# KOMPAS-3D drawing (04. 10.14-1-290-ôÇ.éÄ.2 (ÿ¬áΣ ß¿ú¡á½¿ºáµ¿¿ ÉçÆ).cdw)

Views: Вид спереди. Двери не показаны, Вид 2, Вид 3
Referenced files: ЗРУ 10кВ ПС527.cdw
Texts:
  Корюкин Александр Сергеевич
  Последний номер ВЭ
  Последний номер ВЭ в сечении
  Колонна
  Лестница
  Марш ЛМФ42.15.18-5 ГОСТ 9818-85
  Марш ЛМП57.11.18-5 ГОСТ 9818-85
  Марш ЛМФ42.14.18-5 ГОСТ 9818-85
  Марш ЛМП57.11.14-5 ГОСТ 9818-85
  Марш ЛМ30.12.15-4 ГОСТ 9818-85
  Марш ЛМ30.11.15-4 ГОСТ 9818-85
  Марш ЛМФ42.12.18-5 ГОСТ 9818-85
  Марш ЛМФ49.17.21-5 ГОСТ 9818-85
  Марш ЛМП57.11.15-5 ГОСТ 9818-85
  Марш ЛМ27.12.14-4Л ГОСТ 9818-85
  Марш ЛМФ49.14.21-5 ГОСТ 9818-85
  Марш ЛМФ49.15.21-5 ГОСТ 9818-85
  Марш ЛМП60.11.15-5 ГОСТ 9818-85
  Марш ЛМ27.11.14-4Л ГОСТ 9818-85
  Марш ЛМФ39.14.17-5 ГОСТ 9818-85
  Марш ЛМФ39.15.17-5 ГОСТ 9818-85
  Марш ЛМ27.12.14-4 ГОСТ 9818-85
  Марш ЛМ27.11.14-4 ГОСТ 9818-85
  Марш ЛМФ39.12.17-5 ГОСТ 9818-85
  Марш ЛМП57.11.17-5 ГОСТ 9818-85
  Марш ЛМП60.11.17-5 ГОСТ 9818-85
  Стена
  Блоки фундаментные 130
  Блоки фундаментные 400
  Блоки фундаментные 500
  Блоки фундаментные 600
  Текст на чертеже
  Размерные надписи
  Шероховатость
  Линия-выноска #1
  Линия-выноска #2
  Линия-выноска #3
  Отклонения формы и база
  Заголовок таблицы
  Ячейка таблицы
  Стрелка вида
  Обозначение изменения
  Фигурная скобка
  Номер узла
  Марка координационной оси
  VRCB
  Выносная надпись
  Обозначение узла
  Марка/позиционное обозначение с линией-выноской
  Марка/позиционное обозначение на линии
  Марка/позиционное обозначение без линии-выноски
  Лит-Масса-Масштаб
  Материал-Предприятие
  Normal
  Additional DXF text style 0
  Обычный
  Термин
  Список определений
  Адрес
  Цитаты
  Форматированный
  Courier New
  Z-конец формы
  Z-начало формы
  Подпись в квадратике
  цепи
  Title Specification
  Body Specification ( left align )
  Body Specificaton ( centered )
  Body Text
  ссылки
  табл
  Без имени
  Тексты. 3,2
  ЗОНА_привяз
  heading 1
  Знак Знак Знак Знак Знак Знак
  Verdana
  Body Text 3
  Title
  txt
  MS Sans Serif
  Simplex
  Txt
  ТекстШаг1
  Денис
  heading 8
  heading 3
  heading 6
  heading 7
  russ
  ООббыыччнныыйй
  ТТееррммиинн
  ССппииссоокк ооппррееддееллеенниийй
  ААддрреесс
  ЦЦииттааттыы
  ФФооррммааттиирроовваанннныыйй
  Z-ккооннеецц ффооррммыы
  Z-ннааччааллоо ффооррммыы
  Абзац Знак
  heading 2
  heading 4
  heading 5
  heading 9
  Клеммник текст
  текст переноса
  Маркировка
  клеммы, контакты
  тексты табл
  AGOpus
  footer
  Definition Term
  Definition List
  Address
  Blockquote
  Preformatted
  z-Bottom of Form
  z-Top of Form
  Состав чартежа
  ячейка табл.
  маркировка
  Аппараты
  rustxt
  Table Contents
  Table Heading
  Tahoma
  подписи
  Ссылки
  Пояснения
  Монтаж.ед.
  ахтунг!!
  полезная площадь
  лампочки
  Фасад шкафа
  Перечень надписей
  Монтажная
  единица
  KH1
  Позиционное
  обозначение
  по схеме
  КН2
  SG1
  В рамке под
  аппаратом
  Место
  надписи
  KH1. Отключение В-110 1Т от РЗТ (ЭМО1)
  Текст надписи
  KH2. Отключение В-110 1Т от РЗТ (ЭМО2)
  SG1. Токовые цепи РЗТ 1Т
  KH1. Отключение В-110 2Т от РЗТ (ЭМО1)
  KH2. Отключение В-110 2Т от РЗТ (ЭМО2)
  SG1. Токовые цепи РЗТ 2Т
  Наименование монтажной единицы
  Номер монтажной единицы
  Номер схемы электрической
  принципиальной
  Номер чертежа клеммного ряда
  Перечень монтажных единиц и чертежей
  Сигнализация РЗТ
  Примечания:
  шкафа - серый;
  изолированным проводом сечением не менее 1,5 мм 2 , токовые цепи - сечением 4 мм 2 ;
  основной конструкции на болты. Медная полоса должна обеспечивать возможность присоединения
  кабелей с целью концевой разделки и заземления экранов с помощью металлических зажимов.
  CONTINUOUS0
  GOST2.303 6_RGB_0_0_0_SC_0.1_THICK_0.13
  POLYLINE_STYLE_0.18_RGB_0_0_0
  K5LT_BASIC_RGB_0_0_255_THICK_0.6
  Стили документа
  Общеподстанционный пункт
  управления тип III из
  унифицированных конструкций
  Общий вид щита  управления
  с мнемонической схемой
  Чертеж общего вида
  Шкаф сигнализации РЗТ.
  Чертёж общего вида.
  Н.контр
  Борисов
  Разраб.
  Реконструкция ПС 110 кВ Опорная
  (замена трансформаторов 16МВА на 40МВА)
Dimensions and other numbers on the sheet: 10/14-1-290-УА.ВО.2; 5; 0; 7; 3,2_зона не привяз; 3,2 (надписи); 2.5; 3,2_; 2,5_3; 2,5 (контакты, клеммы); 2,5_01; 3,5_01; 2,3_; 5_заголовок; 3,5_tabl; 3.5; 2,5; 1,8; 3,2; 2.5 курсив; 2,5 грязносинь; 3,5; 3,2 элементы; 3,2 линия; 3,2 таблица; 3.2 маркировка; 2.5_Э5_надписи; 2.5_Э5_ссылки; 2.5_кабель; 3.2; 2.5 надписи; 3,2 (Зоны); 5,0_белый_подчёркнутый; 3.2 фиол; 3.2 (текст); 110 кВ; 6 кВ; 35 кВ; 01; 02; 10/14-1-290-УА.Э3.2; 10/14-1-290-УА.Э4.2; 01-KH1; 30; 02-KH1; 01-KH2; 02-KH2; 300; 500; 400; 100; 230; 380; 01-SG1; 02-SG1; 90; 1:1; 86/02-19-01-290-УА.ВО.2-; 11.12; 1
